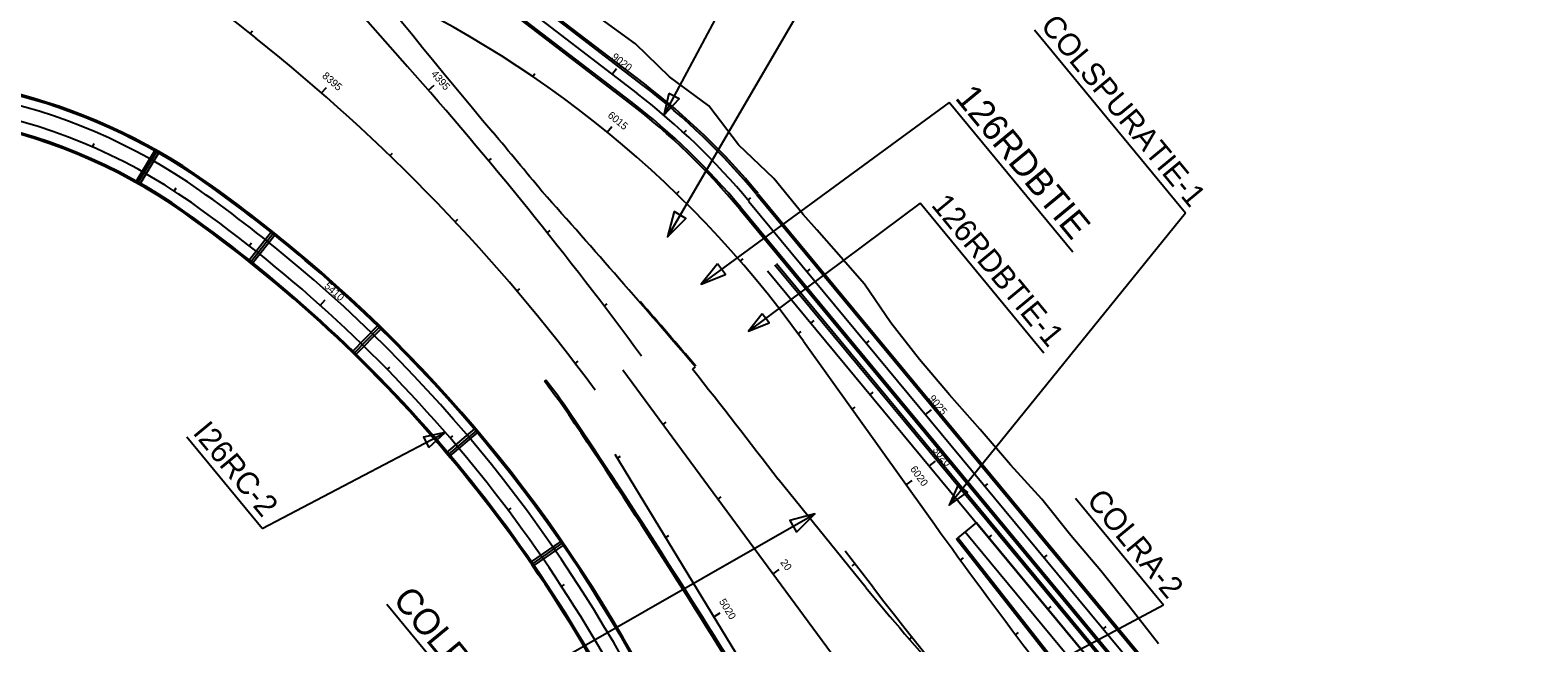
# Model space of a CAD drawing. Extents: x 1944333 to 1975203, y 788957 to 827579.
# Drawn here: x 1969597 to 1971221, y 796981 to 797640 of the extents above; entities that cross this region are included whole.
import ezdxf

# ---------------------------------------------------------------- set-up
doc = ezdxf.new("R2010")
doc.units = 0
for name, color, linetype in [('BR_CENTER LINES', 7, 'Continuous'), ('BR_CONCRETE', 7, 'Continuous'), ('RD_HC_CL_Rel', 7, 'Continuous'), ('RD_HC_Data_Tic_Rel', 7, 'Continuous'), ('RD_HC_TX_Rel_Sta50', 7, 'Continuous'), ('RD_PD_ALT1_TrvlWay', 7, 'Continuous'), ('RD_PD_CstnLmt', 7, 'Continuous'), ('RD_PD_GR', 7, 'Continuous'), ('RD_PD_PaveShd', 7, 'Continuous'), ('RD_PD_WallFill', 7, 'Continuous'), ('RD_TX_RoadID', 7, 'Continuous')]:
    doc.layers.add(name, color=color, linetype=linetype)

msp = doc.modelspace()

# ---------------------------------------------------------------- linework, layer by layer
at = {"layer": 'BR_CENTER LINES'}
for p, q in [((1969733.5, 797510.2), (1969712.9, 797476)), ((1969834.3, 797390.6), (1969859, 797422.1)), ((1969945.8, 797292.4), (1969973.6, 797321.1)), ((1970077.7, 797209.5), (1970047.2, 797183.7)), ((1970170.4, 797088.4), (1970137.5, 797065.6))]:
    msp.add_line(p, q, dxfattribs=at)
at = {"layer": 'BR_CONCRETE'}
for p, q in [((1969731.4, 797511.5), (1969710.7, 797477.2)), ((1969735.7, 797508.9), (1969715, 797474.7)), ((1969735.7, 797508.9), (1969731.4, 797511.5)), ((1969710.7, 797477.2), (1969715, 797474.7)), ((1969832.3, 797392.2), (1969857, 797423.6)), ((1969836.2, 797389.1), (1969860.9, 797420.5)), ((1969860.9, 797420.5), (1969857, 797423.6)), ((1969836.2, 797389.1), (1969832.3, 797392.2)), ((1969944, 797294.1), (1969971.8, 797322.8)), ((1969975.4, 797319.3), (1969971.8, 797322.8)), ((1969947.6, 797290.7), (1969975.4, 797319.3)), ((1969947.6, 797290.7), (1969944, 797294.1)), ((1970076.1, 797211.4), (1970045.6, 797185.6)), ((1970079.3, 797207.6), (1970076.1, 797211.4)), ((1970079.3, 797207.6), (1970048.8, 797181.8)), ((1970045.6, 797185.6), (1970048.8, 797181.8)), ((1970169, 797090.4), (1970136.1, 797067.7)), ((1970171.9, 797086.3), (1970138.9, 797063.6)), ((1970171.9, 797086.3), (1970169, 797090.4)), ((1970136.1, 797067.7), (1970138.9, 797063.6))]:
    msp.add_line(p, q, dxfattribs=at)
for centre, radius, start, end in [((1969424.5, 796964.6), 627.6, 54.7761, 139.9591), ((1969424.5, 796964.6), 626, 54.7761, 139.7268), ((1969424.5, 796964.6), 588, 54.7761, 157.246), ((1969424.5, 796964.6), 586.4, 54.7761, 157.246), ((1968885.8, 796201.6), 1560, 49.7691, 54.7761), ((1968885.8, 796201.6), 1561.6, 49.7691, 54.7761), ((1968885.8, 796201.6), 1520.4, 24.6902, 54.7761), ((1968885.8, 796201.6), 1522, 24.6902, 54.7761), ((1968885.8, 796201.6), 1560, 24.6902, 49.7691), ((1968885.8, 796201.6), 1561.6, 24.6902, 49.7691)]:
    msp.add_arc(centre, radius, start, end, dxfattribs=at)
at = {"layer": 'RD_HC_CL_Rel'}
for p, q in [((1969086.4, 798230.6), (1969840.1, 797631.9)), ((1969602, 798055.5), (1970003.6, 797601.5)), ((1969982.4, 797778.2), (1970250.8, 797572.2)), ((1970371.4, 797456.1), (1970870.2, 796854.8)), ((1970391.3, 797381.2), (1970774.1, 796919.7)), ((1970430, 797305.7), (1970564.8, 797117.4)), ((1970235.6, 797274.6), (1971221.4, 795937.4)), ((1970226.8, 797183.8), (1970493.6, 796746.7)), ((1970505.6, 797039.9), (1970475.2, 797079.4))]:
    msp.add_line(p, q, dxfattribs=at)
for centre, radius, start, end in [((1969482, 796626.9), 1166, 35.6021, 163.611), ((1968596, 796065.9), 2000, 36.3977, 51.5342), ((1966623.9, 794612.1), 4512, 36.3977, 41.4938), ((1969794.2, 796977.3), 750, 39.6755, 52.4907), ((1969424.5, 796964.6), 600, 54.7761, 157.246), ((1968885.8, 796201.6), 1534, 24.6902, 54.7761), ((1976020.6, 801023.6), 6710, 215.60211, 218.56681), ((1973505.9, 799345.7), 3784, 217.5434, 226.4244)]:
    msp.add_arc(centre, radius, start, end, dxfattribs=at)
at = {"layer": 'RD_HC_Data_Tic_Rel'}
for p, q in [((1969834, 797636.7), (1969836.5, 797639.8)), ((1970223.8, 797592.9), (1970228.7, 797599.3)), ((1970138.5, 797590.5), (1970140.7, 797593.8)), ((1969910.9, 797572.9), (1969916.2, 797578.9)), ((1970026.1, 797575.8), (1970032.1, 797581.1)), ((1970218.6, 797530.7), (1970223.6, 797536.9)), ((1969664.2, 797514.6), (1969665.8, 797518.3)), ((1970301.3, 797529.8), (1970304, 797532.7)), ((1969984.6, 797505.3), (1969987.4, 797508.1)), ((1970090.9, 797499.7), (1970094, 797502.3)), ((1969752.1, 797467.2), (1969754.3, 797470.6)), ((1970293.3, 797464.3), (1970296.1, 797467.2)), ((1970370.3, 797457.5), (1970373.4, 797460)), ((1970054.8, 797434.1), (1970057.7, 797436.8)), ((1970154.1, 797422.2), (1970157.2, 797424.6)), ((1969832.9, 797408.3), (1969835.4, 797411.4)), ((1970362.1, 797391.7), (1970365.1, 797394.3)), ((1970434.1, 797380.5), (1970437.2, 797383)), ((1970121.4, 797359.4), (1970124.4, 797362)), ((1969909.5, 797344), (1969914.8, 797350)), ((1970215.5, 797343.2), (1970218.7, 797345.7)), ((1970438.4, 797325.2), (1970441.5, 797327.7)), ((1970424.3, 797313.5), (1970427.6, 797315.9)), ((1970498, 797303.5), (1970501.1, 797306.1)), ((1969981.7, 797274.9), (1969984.6, 797277.7)), ((1970184.1, 797281.6), (1970187.3, 797284)), ((1970502.3, 797248.2), (1970505.4, 797250.7)), ((1970482.6, 797232.2), (1970485.8, 797234.6)), ((1970561.8, 797226.6), (1970568, 797231.7)), ((1970278.9, 797215.9), (1970282.1, 797218.3)), ((1970049.3, 797201.2), (1970052.4, 797203.8)), ((1970229.4, 797179.5), (1970232.8, 797181.6)), ((1970566.1, 797171.2), (1970572.3, 797176.3)), ((1970540.8, 797150.9), (1970547.3, 797155.6)), ((1970625.7, 797149.6), (1970628.7, 797152.1)), ((1970338.2, 797135.4), (1970341.5, 797137.8)), ((1970112, 797123.3), (1970115.2, 797125.7)), ((1970281.5, 797094.1), (1970284.9, 797096.2)), ((1970630, 797094.3), (1970633.1, 797096.8)), ((1970485.6, 797065.9), (1970482.4, 797063.5)), ((1970599.2, 797069.8), (1970602.5, 797072.1)), ((1970689.5, 797072.6), (1970692.6, 797075.2)), ((1970397.6, 797054.9), (1970404, 797059.7)), ((1970169.4, 797041.5), (1970172.8, 797043.7)), ((1970693.8, 797017.3), (1970696.9, 797019.8)), ((1970333.6, 797008.8), (1970340.5, 797012.9)), ((1970753.3, 796995.7), (1970756.4, 796998.2)), ((1970547, 796987), (1970543.8, 796984.5)), ((1970658.7, 796989.4), (1970661.9, 796991.8))]:
    msp.add_line(p, q, dxfattribs=at)
at = {"layer": 'RD_PD_ALT1_TrvlWay'}
for p, q in [((1970244.1, 797563.5), (1969975.7, 797769.5)), ((1970257.5, 797580.9), (1970131.9, 797677.3)), ((1970379.9, 797463.1), (1970878.6, 796861.8)), ((1970363, 797449.1), (1970861.7, 796847.8)), ((1970616.6, 797110.3), (1970596.6, 797093.7)), ((1970604.3, 797100.1), (1970762.2, 796909.8)), ((1970616.6, 797110.3), (1970774.5, 796920))]:
    msp.add_line(p, q, dxfattribs=at)
for centre, radius, start, end in [((1969424.5, 796964.6), 616, 54.7761, 150.713), ((1969794.2, 796977.3), 761, 39.6755, 52.4907), ((1969794.2, 796977.3), 739, 39.6755, 52.4907), ((1968885.8, 796201.6), 1534, 24.6902, 54.7761), ((1968885.8, 796201.6), 1550, 49.7691, 54.7761), ((1968885.8, 796201.6), 1550, 24.6902, 49.7691)]:
    msp.add_arc(centre, radius, start, end, dxfattribs=at)
at = {"layer": 'RD_PD_CstnLmt'}
msp.add_lwpolyline([(1970812.6, 796979.8), (1970781.8, 797019.3), (1970750.5, 797058.2), (1970718.1, 797096.4), (1970687, 797135.5), (1970653.2, 797172.4), (1970620.7, 797210.4), (1970587.4, 797247.8), (1970555.1, 797285.9), (1970524.1, 797325.2), (1970496, 797366.8), (1970463, 797404.5), (1970444.7, 797425.5), (1970429.8, 797441.8), (1970398.1, 797480.6), (1970360.3, 797516.9), (1970328.1, 797559), (1970285.8, 797590.3), (1970249.1, 797625.8), (1970208.6, 797655.2)], dxfattribs=at)
at = {"layer": 'RD_PD_GR'}
msp.add_arc((1961563, 789787.4), 11519.7, 40.56466, 41.02244, dxfattribs=at)
at = {"layer": 'RD_PD_PaveShd'}
for p, q in [((1970242.9, 797561.9), (1969974.5, 797767.9)), ((1970258.7, 797582.5), (1970133.2, 797678.9)), ((1970381.4, 797464.4), (1970880.2, 796863.1)), ((1970361.4, 797447.8), (1970860.2, 796846.5)), ((1970313.5, 797278.1), (1970310.5, 797275.5)), ((1970497.3, 797040.4), (1970402.8, 797157))]:
    msp.add_line(p, q, dxfattribs=at)
for centre, radius, start, end in [((1978894.5, 804897.7), 11476, 217.23533, 219.93701), ((1969794.2, 796977.3), 763, 39.6755, 52.4907), ((1969794.2, 796977.3), 737, 39.6755, 52.4907), ((1961259.3, 790132.9), 11524, 39.52221, 39.93701), ((1961563, 789787.4), 11518.8, 40.56466, 41.81015), ((1961259.3, 790132.9), 11530, 37.53057, 38.27801), ((1972045.7, 798296.9), 1994, 219.0581, 222.7981)]:
    msp.add_arc(centre, radius, start, end, dxfattribs=at)
at = {"layer": 'RD_PD_WallFill'}
for p, q in [((1970399.4, 797387.9), (1970782.2, 796926.4)), ((1970400.9, 797389.2), (1970783.8, 796927.7)), ((1970152.5, 797263.6), (1970151, 797262.4)), ((1970595.1, 797092.5), (1970596.6, 797093.7)), ((1970813.2, 796814.8), (1970595.1, 797092.5)), ((1970814.7, 796816.1), (1970596.6, 797093.7))]:
    msp.add_line(p, q, dxfattribs=at)
for centre, radius, start, end in [((1968596, 796065.9), 1962, 36.6231, 37.5771), ((1968596, 796065.9), 1964, 36.6218, 37.5771), ((1963181.8, 792526), 8428, 31.39766, 33.97915), ((1963181.8, 792526), 8430, 31.39766, 33.97947)]:
    msp.add_arc(centre, radius, start, end, dxfattribs=at)
at = {"layer": 'RD_TX_RoadID'}
for p, q in [((1970841.9, 797443.3), (1970679.2, 797640.4)), ((1970720.2, 797401.4), (1970587.1, 797562.7)), ((1970689.3, 797292.6), (1970555.9, 797454.1)), ((1969846.9, 797104), (1969765.8, 797202.2)), ((1970818, 797021.4), (1970723.2, 797136.2)), ((1970074.5, 796909.4), (1969981.3, 797022.2))]:
    msp.add_line(p, q, dxfattribs=at)
for points in [[(1970457.1, 797715.4), (1970283.5, 797418.1)], [(1970351.6, 797683.7), (1970279.7, 797548.9)], [(1970587.1, 797562.7), (1970320, 797367.1)], [(1970555.9, 797454.1), (1970370.9, 797316.3)], [(1970841.9, 797443.3), (1970587.3, 797128.9)], [(1969846.9, 797104), (1970044.1, 797207.3)], [(1970074.5, 796909.4), (1970442.4, 797119.5)], [(1970818, 797021.4), (1970605.5, 796907.8)]]:
    msp.add_lwpolyline(points, dxfattribs=at)
for points in [[(1970285.2, 797572.2), (1970279.7, 797548.9), (1970296.1, 797566.4)], [(1970290.9, 797445.1), (1970283.5, 797418.1), (1970303.4, 797437.8)], [(1970337.5, 797388.9), (1970320, 797367.1), (1970346.1, 797377.2)], [(1970385.8, 797335.1), (1970370.9, 797316.3), (1970393.2, 797325.2)], [(1970026.4, 797191.1), (1970044.1, 797207.3), (1970020.7, 797202.1)], [(1970597, 797150.8), (1970587.3, 797128.9), (1970606.7, 797143)], [(1970422.5, 797099.8), (1970442.4, 797119.5), (1970415.3, 797112.4)]]:
    msp.add_lwpolyline(points, close=True, dxfattribs=at)

# ---------------------------------------------------------------- texts
at = {"layer": 'RD_HC_TX_Rel_Sta50'}
for s, rotation, p in [('9020', 322.4907, (1970222.7, 797610.2)), ('8395', 318.893, (1969910.9, 797590.2)), ('4395', 311.0602, (1970028.4, 797592.9)), ('6015', 320.8201, (1970218.5, 797547.5)), ('5410', 318.1359, (1969913.2, 797364)), ('9025', 309.6755, (1970564.5, 797243.6)), ('3020', 309.6755, (1970568.9, 797188.3)), ('6020', 305.6021, (1970544.7, 797167.8)), ('20', 306.3977, (1970404.7, 797067.2)), ('5020', 301.3977, (1970338.8, 797025.3))]:
    msp.add_text(s, height=8, rotation=rotation, dxfattribs=at).set_placement(p)
at = {"layer": 'RD_TX_RoadID'}
for s, height, p in [('COLSPURATIE-1', 24, (1970684.6, 797644.8)), ('126RDBTIE', 28, (1970592.5, 797567.1)), (' 126RDBTIE-1', 24, (1970561.3, 797458.6)), ('I26RC-2 ', 24, (1969771.2, 797206.7)), (' COLRA-2', 24, (1970728.6, 797140.7)), ('COLRA ', 28, (1969986.7, 797026.7))]:
    msp.add_text(s, height=height, rotation=309.5517, dxfattribs=at).set_placement(p)

doc.saveas('drawing.dxf')
